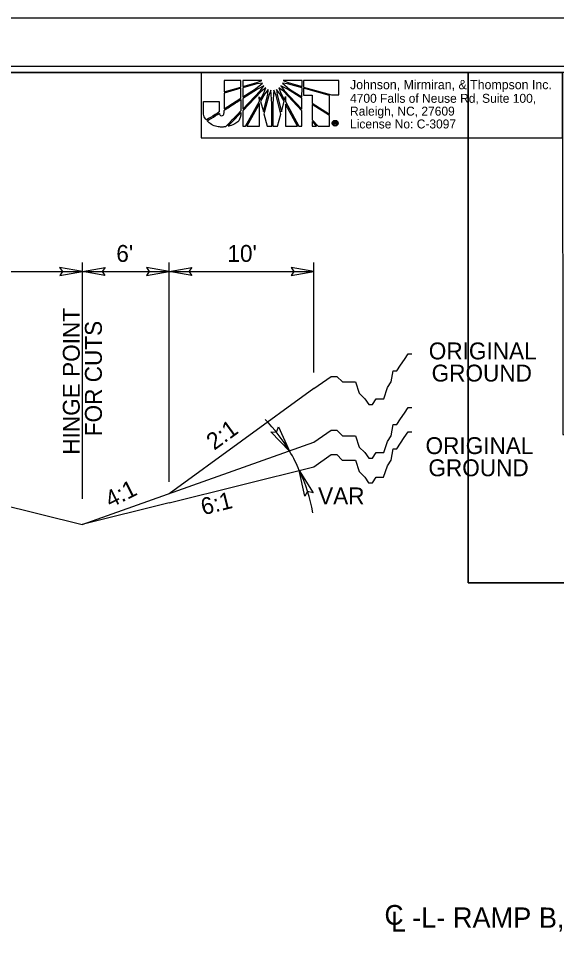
# Model space of a CAD drawing. Extents: x 1640342 to 1730599, y 538663 to 843747.
# Drawn here: x 1730088.8 to 1730133.5, y 539530.7 to 539606.6 of the extents above; entities that cross this region are included whole.
import ezdxf

# ---------------------------------------------------------------- set-up
doc = ezdxf.new("R2010")
doc.units = 0
for name, color, linetype in [('Default', 7, 'Continuous'), ('Prop Dimension Text', 7, 'Continuous'), ('Sheet Clip Boundary CELL', 7, 'Continuous'), ('Sheet Layout Plan Border', 7, 'Continuous'), ('Sheet Plan CELL', 7, 'Continuous'), ('Sheet Plan Layout CELL', 7, 'Continuous'), ('Sheet Plot Border Inside CELL', 7, 'Continuous'), ('Sheet Plot Border Outside CELL', 7, 'Continuous'), ('Typical Hinge Slope Interstate CELL', 7, 'Continuous'), ('Typical Pavement Slope CELL', 7, 'Continuous'), ('Typical Text Centerline CELL', 7, 'Continuous')]:
    doc.layers.add(name, color=color, linetype=linetype)

msp = doc.modelspace()

# ---------------------------------------------------------------- linework, layer by layer
at = {"layer": 'Default'}
for p, q in [((1730094.148, 539566.8), (1730094.148, 539586.384)), ((1730101.348, 539568.206), (1730101.348, 539586.384)), ((1730113.348, 539577.278), (1730113.348, 539586.384)), ((1730072.54, 539585.645), (1730094.141, 539585.645)), ((1730094.141, 539585.645), (1730101.341, 539585.645)), ((1730101.341, 539585.645), (1730113.341, 539585.645))]:
    msp.add_line(p, q, dxfattribs=at)
for points in [[(1730092.274, 539585.324), (1730094.148, 539585.647), (1730092.264, 539585.98), (1730092.503, 539585.647)], [(1730096.022, 539585.324), (1730094.148, 539585.647), (1730096.033, 539585.98), (1730095.793, 539585.647)], [(1730099.474, 539585.324), (1730101.348, 539585.647), (1730099.464, 539585.98), (1730099.703, 539585.647)], [(1730103.222, 539585.324), (1730101.348, 539585.647), (1730103.233, 539585.98), (1730102.993, 539585.647)], [(1730111.467, 539585.322), (1730113.341, 539585.645), (1730111.456, 539585.978), (1730111.696, 539585.645)], [(1730110.407, 539572.756), (1730111.316, 539570.761), (1730109.776, 539572.34), (1730110.248, 539572.328)], [(1730112.59, 539567.014), (1730112.124, 539569.155), (1730113.295, 539567.286), (1730112.835, 539567.398)], [(1730112.59, 539567.014), (1730112.124, 539569.155), (1730113.295, 539567.286), (1730112.835, 539567.398)]]:
    msp.add_lwpolyline(points, close=True, dxfattribs=at)
at = {"layer": 'Prop Dimension Text'}
for p, q in [((1730107.302, 539601.48), (1730105.899, 539601.478)), ((1730105.899, 539601.478), (1730105.9, 539600.548)), ((1730107.302, 539600.938), (1730107.302, 539601.48)), ((1730109.027, 539601.488), (1730107.448, 539601.487)), ((1730107.448, 539601.487), (1730107.448, 539600.984)), ((1730107.448, 539600.984), (1730108.624, 539601.31)), ((1730108.502, 539600.784), (1730109.082, 539601.257)), ((1730108.624, 539601.31), (1730109.027, 539601.488)), ((1730109.082, 539601.257), (1730108.624, 539601.201)), ((1730110.736, 539601.258), (1730111.324, 539600.777)), ((1730111.169, 539601.203), (1730110.736, 539601.258)), ((1730112.37, 539601.485), (1730110.814, 539601.49)), ((1730110.814, 539601.49), (1730111.208, 539601.305)), ((1730111.208, 539601.305), (1730112.37, 539600.98)), ((1730112.37, 539600.98), (1730112.37, 539601.485)), ((1730115.428, 539601.494), (1730112.479, 539601.492)), ((1730112.479, 539601.492), (1730112.479, 539600.95)), ((1730115.43, 539600.286), (1730115.428, 539601.494)), ((1730105.9, 539600.548), (1730107.302, 539600.938)), ((1730107.302, 539600.836), (1730105.9, 539600.441)), ((1730107.303, 539600.023), (1730107.302, 539600.836)), ((1730108.624, 539601.201), (1730107.448, 539600.876)), ((1730107.448, 539600.876), (1730107.449, 539600.116)), ((1730107.449, 539600.116), (1730108.502, 539600.784)), ((1730108.664, 539600.768), (1730107.449, 539599.993)), ((1730107.45, 539599.118), (1730108.928, 539600.659)), ((1730108.988, 539600.583), (1730107.45, 539598.97)), ((1730109.198, 539601.039), (1730108.664, 539600.768)), ((1730108.928, 539600.659), (1730109.198, 539601.039)), ((1730109.361, 539600.87), (1730108.988, 539600.583)), ((1730109.19, 539600.421), (1730109.361, 539600.87)), ((1730109.562, 539600.746), (1730109.285, 539600.389)), ((1730109.523, 539600.313), (1730109.562, 539600.746)), ((1730109.794, 539600.683), (1730109.602, 539600.234)), ((1730109.855, 539599.577), (1730109.794, 539600.683)), ((1730110.025, 539600.684), (1730109.954, 539599.577)), ((1730110.211, 539600.235), (1730110.025, 539600.684)), ((1730110.25, 539600.746), (1730110.296, 539600.297)), ((1730110.521, 539600.39), (1730110.25, 539600.746)), ((1730110.449, 539600.871), (1730110.621, 539600.422)), ((1730110.822, 539600.585), (1730110.449, 539600.871)), ((1730110.613, 539601.041), (1730110.884, 539600.654)), ((1730111.155, 539600.77), (1730110.613, 539601.041)), ((1730112.363, 539598.961), (1730110.822, 539600.585)), ((1730110.884, 539600.654), (1730112.363, 539599.107)), ((1730112.362, 539600.005), (1730111.155, 539600.77)), ((1730112.37, 539600.873), (1730111.169, 539601.203)), ((1730111.324, 539600.777), (1730112.362, 539600.13)), ((1730112.362, 539600.13), (1730112.37, 539600.873)), ((1730112.479, 539600.95), (1730112.479, 539600.934)), ((1730112.479, 539600.934), (1730114.802, 539600.285)), ((1730112.479, 539600.85), (1730112.479, 539600.841)), ((1730114.654, 539600.232), (1730112.479, 539600.85)), ((1730112.479, 539600.841), (1730112.48, 539600.276)), ((1730105.9, 539600.441), (1730105.901, 539599.133)), ((1730105.901, 539599.133), (1730107.303, 539600.023)), ((1730107.449, 539599.993), (1730107.45, 539599.118)), ((1730107.683, 539597.697), (1730108.827, 539599.77)), ((1730108.827, 539599.77), (1730108.826, 539600.141)), ((1730108.826, 539600.141), (1730108.896, 539599.886)), ((1730108.896, 539599.886), (1730109.19, 539600.421)), ((1730109.285, 539600.389), (1730108.936, 539599.754)), ((1730108.936, 539599.754), (1730109.161, 539598.912)), ((1730109.161, 539598.912), (1730109.523, 539600.313)), ((1730109.602, 539600.234), (1730109.208, 539598.717)), ((1730110.615, 539598.695), (1730110.211, 539600.235)), ((1730110.296, 539600.297), (1730110.661, 539598.881)), ((1730110.885, 539599.733), (1730110.521, 539600.39)), ((1730110.621, 539600.422), (1730110.922, 539599.865)), ((1730110.661, 539598.881), (1730110.885, 539599.733)), ((1730110.922, 539599.865), (1730110.994, 539600.143)), ((1730110.994, 539600.143), (1730110.994, 539599.733)), ((1730110.994, 539599.733), (1730112.116, 539597.701)), ((1730112.363, 539599.107), (1730112.362, 539600.005)), ((1730112.48, 539600.276), (1730113.2, 539600.277)), ((1730113.2, 539600.277), (1730113.201, 539599.603)), ((1730114.655, 539598.683), (1730114.654, 539600.232)), ((1730114.802, 539600.285), (1730115.43, 539600.286)), ((1730107.45, 539598.97), (1730107.451, 539597.697)), ((1730108.827, 539599.569), (1730107.792, 539597.697)), ((1730108.838, 539597.698), (1730108.827, 539599.569)), ((1730109.857, 539597.706), (1730109.855, 539599.577)), ((1730109.954, 539599.577), (1730109.956, 539597.706)), ((1730112.001, 539597.708), (1730110.994, 539599.531)), ((1730110.994, 539599.531), (1730110.996, 539597.707)), ((1730112.364, 539597.701), (1730112.363, 539598.961)), ((1730113.201, 539599.603), (1730114.655, 539598.683)), ((1730113.201, 539599.487), (1730113.202, 539598.232)), ((1730114.655, 539598.574), (1730113.201, 539599.487)), ((1730109.208, 539598.717), (1730109.472, 539597.706)), ((1730110.345, 539597.706), (1730110.615, 539598.695)), ((1730113.202, 539598.232), (1730113.705, 539597.703)), ((1730114.656, 539597.704), (1730114.655, 539598.574)), ((1730107.451, 539597.697), (1730107.683, 539597.697)), ((1730107.792, 539597.697), (1730108.838, 539597.698)), ((1730109.472, 539597.706), (1730109.857, 539597.706)), ((1730109.956, 539597.706), (1730110.345, 539597.706)), ((1730110.996, 539597.707), (1730112.001, 539597.708)), ((1730112.116, 539597.701), (1730112.364, 539597.701)), ((1730113.566, 539597.703), (1730113.202, 539598.096)), ((1730113.202, 539598.096), (1730113.202, 539597.702)), ((1730113.202, 539597.702), (1730113.566, 539597.703)), ((1730113.705, 539597.703), (1730114.656, 539597.704)), ((1730115.026, 539597.836), (1730115.025, 539598.051)), ((1730115.025, 539598.051), (1730115.113, 539598.051)), ((1730115.074, 539597.836), (1730115.026, 539597.836)), ((1730115.113, 539598.01), (1730115.074, 539598.01)), ((1730115.074, 539598.01), (1730115.074, 539597.959)), ((1730115.074, 539597.959), (1730115.113, 539597.959)), ((1730115.113, 539597.92), (1730115.074, 539597.92)), ((1730115.074, 539597.92), (1730115.074, 539597.836)), ((1730115.113, 539598.178), (1730115.113, 539598.133)), ((1730115.113, 539598.133), (1730115.113, 539598.178)), ((1730115.113, 539598.051), (1730115.113, 539598.01)), ((1730115.113, 539598.01), (1730115.113, 539598.051)), ((1730115.113, 539598.051), (1730115.127, 539598.051)), ((1730115.119, 539598.01), (1730115.113, 539598.01)), ((1730115.113, 539597.959), (1730115.113, 539597.92)), ((1730115.113, 539597.92), (1730115.113, 539597.959)), ((1730115.113, 539597.959), (1730115.115, 539597.959)), ((1730115.115, 539597.92), (1730115.113, 539597.92)), ((1730115.113, 539597.753), (1730115.114, 539597.706)), ((1730115.114, 539597.706), (1730115.113, 539597.753)), ((1730115.113, 539597.753), (1730115.115, 539597.753)), ((1730115.115, 539597.706), (1730115.114, 539597.706))]:
    msp.add_line(p, q, dxfattribs=at)
msp.add_lwpolyline([(1730104.001, 539596.732), (1730133.983, 539596.732), (1730133.983, 539602.142), (1730104.001, 539602.142)], close=True, dxfattribs=at)
for points in [[(1730105.9, 539600.548), (1730107.302, 539600.938), (1730107.302, 539601.48), (1730105.899, 539601.478), (1730105.9, 539600.548)], [(1730108.624, 539601.31), (1730109.027, 539601.488), (1730107.448, 539601.487), (1730107.448, 539600.984), (1730108.624, 539601.31)], [(1730107.448, 539600.876), (1730107.449, 539600.116), (1730108.502, 539600.784), (1730109.082, 539601.257), (1730108.624, 539601.201), (1730107.448, 539600.876)], [(1730110.736, 539601.258), (1730111.324, 539600.777), (1730112.362, 539600.13), (1730112.37, 539600.873), (1730111.169, 539601.203), (1730110.736, 539601.258)], [(1730111.208, 539601.305), (1730112.37, 539600.98), (1730112.37, 539601.485), (1730110.814, 539601.49), (1730111.208, 539601.305)], [(1730115.428, 539601.494), (1730112.479, 539601.492), (1730112.479, 539600.95), (1730112.479, 539600.934), (1730114.802, 539600.285), (1730115.43, 539600.286), (1730115.428, 539601.494)], [(1730105.901, 539599.133), (1730107.303, 539600.023), (1730107.302, 539600.836), (1730105.9, 539600.441), (1730105.901, 539599.133)], [(1730107.449, 539599.993), (1730107.45, 539599.118), (1730108.928, 539600.659), (1730109.198, 539601.039), (1730108.664, 539600.768), (1730107.449, 539599.993)], [(1730109.361, 539600.87), (1730108.988, 539600.583), (1730107.45, 539598.97), (1730107.451, 539597.697), (1730107.683, 539597.697), (1730108.827, 539599.77), (1730108.826, 539600.141), (1730108.896, 539599.886), (1730109.19, 539600.421), (1730109.361, 539600.87)], [(1730109.562, 539600.746), (1730109.285, 539600.389), (1730108.936, 539599.754), (1730109.161, 539598.912), (1730109.523, 539600.313), (1730109.562, 539600.746)], [(1730109.602, 539600.234), (1730109.208, 539598.717), (1730109.472, 539597.706), (1730109.857, 539597.706), (1730109.855, 539599.577), (1730109.794, 539600.683), (1730109.602, 539600.234)], [(1730110.025, 539600.684), (1730109.954, 539599.577), (1730109.956, 539597.706), (1730110.345, 539597.706), (1730110.615, 539598.695), (1730110.211, 539600.235), (1730110.025, 539600.684)], [(1730110.25, 539600.746), (1730110.296, 539600.297), (1730110.661, 539598.881), (1730110.885, 539599.733), (1730110.521, 539600.39), (1730110.25, 539600.746)], [(1730110.449, 539600.871), (1730110.621, 539600.422), (1730110.922, 539599.865), (1730110.994, 539600.143), (1730110.994, 539599.733), (1730112.116, 539597.701), (1730112.364, 539597.701), (1730112.363, 539598.961), (1730110.822, 539600.585), (1730110.449, 539600.871)], [(1730110.613, 539601.041), (1730110.884, 539600.654), (1730112.363, 539599.107), (1730112.362, 539600.005), (1730111.155, 539600.77), (1730110.613, 539601.041)], [(1730112.479, 539600.85), (1730112.479, 539600.841), (1730112.48, 539600.276), (1730113.2, 539600.277), (1730113.201, 539599.603), (1730114.655, 539598.683), (1730114.654, 539600.232), (1730112.479, 539600.85)], [(1730107.792, 539597.697), (1730108.838, 539597.698), (1730108.827, 539599.569), (1730107.792, 539597.697)], [(1730110.996, 539597.707), (1730112.001, 539597.708), (1730110.994, 539599.531), (1730110.996, 539597.707)], [(1730113.201, 539599.487), (1730113.202, 539598.232), (1730113.705, 539597.703), (1730114.656, 539597.704), (1730114.655, 539598.574), (1730113.201, 539599.487), (1730113.201, 539599.487)], [(1730113.202, 539597.702), (1730113.202, 539597.702), (1730113.566, 539597.703), (1730113.202, 539598.096), (1730113.202, 539597.702)], [(1730115.207, 539597.887), (1730115.207, 539597.875), (1730115.209, 539597.868), (1730115.209, 539597.86), (1730115.215, 539597.837), (1730115.17, 539597.836)]]:
    msp.add_lwpolyline(points, dxfattribs=at)
for points, degree in [([(1730105.497, 539599.735), (1730105.497, 539599.735), (1730104.199, 539599.733), (1730104.199, 539599.733), (1730104.199, 539599.733), (1730104.199, 539598.921), (1730104.199, 539598.921), (1730104.199, 539598.921), (1730104.199, 539598.835), (1730104.199, 539598.835), (1730104.2, 539598.58), (1730104.283, 539598.379), (1730104.432, 539598.21), (1730104.432, 539598.21), (1730105.498, 539598.859), (1730105.498, 539598.876), (1730105.498, 539598.876), (1730105.497, 539599.735), (1730105.497, 539599.735)], 3), ([(1730105.7, 539598.566), (1730105.617, 539598.565), (1730105.545, 539598.612), (1730105.515, 539598.767), (1730105.515, 539598.767), (1730104.508, 539598.143), (1730104.508, 539598.143), (1730104.819, 539597.817), (1730105.314, 539597.623), (1730105.733, 539597.623), (1730105.842, 539597.623), (1730105.925, 539597.633), (1730106.041, 539597.656), (1730106.041, 539597.656), (1730107.304, 539598.963), (1730107.304, 539598.963), (1730107.304, 539598.963), (1730107.303, 539599.908), (1730107.303, 539599.908), (1730107.303, 539599.908), (1730105.901, 539599.015), (1730105.901, 539599.015), (1730105.901, 539598.661), (1730105.816, 539598.566), (1730105.7, 539598.566)], 3), ([(1730105.7, 539598.566), (1730105.617, 539598.565), (1730105.545, 539598.612), (1730105.515, 539598.767), (1730105.515, 539598.767), (1730104.508, 539598.143), (1730104.508, 539598.143), (1730104.819, 539597.817), (1730105.314, 539597.623), (1730105.733, 539597.623), (1730105.842, 539597.623), (1730105.925, 539597.633), (1730106.041, 539597.656), (1730106.041, 539597.656), (1730107.304, 539598.963), (1730107.304, 539598.963), (1730107.304, 539598.963), (1730107.303, 539599.908), (1730107.303, 539599.908), (1730107.303, 539599.908), (1730105.901, 539599.015), (1730105.901, 539599.015), (1730105.901, 539598.661), (1730105.816, 539598.566), (1730105.7, 539598.566)], 3), ([(1730107.304, 539598.815), (1730107.304, 539598.815), (1730106.212, 539597.686), (1730106.212, 539597.686), (1730106.747, 539597.819), (1730107.279, 539598.173), (1730107.304, 539598.815)], 3), ([(1730115.114, 539597.706), (1730115.049, 539597.706), (1730114.993, 539597.729), (1730114.946, 539597.776), (1730114.899, 539597.821), (1730114.875, 539597.877), (1730114.875, 539597.943), (1730114.875, 539598.01), (1730114.899, 539598.066), (1730114.945, 539598.109), (1730114.992, 539598.154), (1730115.047, 539598.178), (1730115.113, 539598.178)], 3), ([(1730115.113, 539598.133), (1730115.06, 539598.133), (1730115.016, 539598.115), (1730114.979, 539598.08), (1730114.942, 539598.043), (1730114.922, 539597.996), (1730114.922, 539597.943), (1730114.922, 539597.891), (1730114.942, 539597.844), (1730114.979, 539597.807), (1730115.016, 539597.77), (1730115.061, 539597.753), (1730115.113, 539597.753)], 3), ([(1730115.113, 539598.178), (1730115.179, 539598.178), (1730115.236, 539598.154), (1730115.283, 539598.11), (1730115.33, 539598.067), (1730115.353, 539598.01), (1730115.353, 539597.944)], 3), ([(1730115.115, 539597.753), (1730115.168, 539597.753), (1730115.213, 539597.77), (1730115.25, 539597.807), (1730115.287, 539597.844), (1730115.306, 539597.891), (1730115.306, 539597.944), (1730115.306, 539597.997), (1730115.287, 539598.043), (1730115.25, 539598.08), (1730115.213, 539598.115), (1730115.168, 539598.133), (1730115.113, 539598.133)], 3), ([(1730115.115, 539597.959), (1730115.146, 539597.959), (1730115.162, 539597.969), (1730115.162, 539597.987), (1730115.162, 539598.002), (1730115.148, 539598.01), (1730115.119, 539598.01)], 3), ([(1730115.353, 539597.944), (1730115.353, 539597.878), (1730115.33, 539597.821), (1730115.285, 539597.774), (1730115.238, 539597.729), (1730115.182, 539597.706), (1730115.115, 539597.706)], 3), ([(1730115.152, 539597.912), (1730115.146, 539597.916), (1730115.135, 539597.92), (1730115.115, 539597.92)], 2), ([(1730115.127, 539598.051), (1730115.181, 539598.051), (1730115.209, 539598.03), (1730115.209, 539597.987), (1730115.209, 539597.967), (1730115.201, 539597.952), (1730115.184, 539597.94)], 3), ([(1730115.17, 539597.836), (1730115.164, 539597.848), (1730115.16, 539597.86), (1730115.16, 539597.875), (1730115.16, 539597.895), (1730115.158, 539597.907), (1730115.152, 539597.912)], 3), ([(1730115.184, 539597.94), (1730115.197, 539597.932), (1730115.205, 539597.915), (1730115.207, 539597.887)], 2)]:
    msp.add_open_spline(points, degree=degree, dxfattribs=at)
at = {"layer": 'Sheet Clip Boundary CELL'}
msp.add_lwpolyline([(1729883.99, 539392.14), (1730163.993, 539392.14), (1730163.993, 539559.842), (1730126.14, 539559.842), (1730126.14, 539602.14), (1729883.99, 539602.14)], close=True, dxfattribs=at)
at = {"layer": 'Sheet Layout Plan Border'}
msp.add_lwpolyline([(1729883.99, 539392.14), (1730163.993, 539392.14), (1730163.993, 539559.842), (1730126.14, 539559.842), (1730126.14, 539602.14), (1729883.99, 539602.14)], close=True, dxfattribs=at)
at = {"layer": 'Sheet Plan CELL'}
for points in [[(1729873.99, 539392.14), (1729873.985, 539602.135), (1730133.983, 539602.142), (1730133.985, 539572.13), (1730173.993, 539572.127), (1730173.993, 539392.14)], [(1730173.998, 539602.14), (1729873.99, 539602.14), (1729873.99, 539392.14), (1730173.993, 539392.14)]]:
    msp.add_lwpolyline(points, close=True, dxfattribs=at)
at = {"layer": 'Sheet Plan Layout CELL'}
for points in [[(1729873.985, 539602.135), (1729873.99, 539392.14), (1730173.99, 539392.14), (1730173.99, 539559.842), (1730126.14, 539559.842), (1730126.14, 539602.14)], [(1730126.14, 539559.842), (1730173.995, 539559.842), (1730174, 539602.14), (1730126.14, 539602.14)]]:
    msp.add_lwpolyline(points, close=True, dxfattribs=at)
at = {"layer": 'Sheet Plot Border Inside CELL'}
msp.add_lwpolyline([(1729843.293, 539391.637), (1730176.49, 539391.64), (1730176.493, 539602.637), (1729843.293, 539602.637)], close=True, dxfattribs=at)
at = {"layer": 'Sheet Plot Border Outside CELL'}
msp.add_lwpolyline([(1729840.693, 539387.637), (1730177.393, 539387.637), (1730177.393, 539606.637), (1729840.693, 539606.637)], close=True, dxfattribs=at)
at = {"layer": 'Typical Hinge Slope Interstate CELL'}
for points in [[(1730113.341, 539575.94), (1730114.783, 539576.952), (1730115.25, 539576.952), (1730115.717, 539576.487), (1730116.028, 539576.487), (1730116.495, 539576.487), (1730116.806, 539576.487), (1730117.118, 539575.55), (1730117.585, 539575.085), (1730117.896, 539574.616), (1730118.207, 539574.616), (1730118.519, 539575.085), (1730118.83, 539575.085), (1730119.141, 539575.085), (1730119.452, 539576.019), (1730119.763, 539576.487), (1730119.92, 539577.421), (1730120.231, 539577.421), (1730120.542, 539577.886), (1730120.853, 539578.355), (1730121.164, 539578.823), (1730121.476, 539578.823)], [(1730113.341, 539571.481), (1730114.783, 539572.493), (1730115.25, 539572.493), (1730115.717, 539572.028), (1730116.028, 539572.028), (1730116.495, 539572.028), (1730116.806, 539572.028), (1730117.118, 539571.091), (1730117.585, 539570.626), (1730117.896, 539570.157), (1730118.207, 539570.157), (1730118.519, 539570.626), (1730118.83, 539570.626), (1730119.141, 539570.626), (1730119.452, 539571.56), (1730119.763, 539572.028), (1730119.92, 539572.962), (1730120.231, 539572.962), (1730120.542, 539573.427), (1730120.853, 539573.895), (1730121.164, 539574.364), (1730121.476, 539574.364)], [(1730113.334, 539569.458), (1730114.776, 539570.47), (1730115.244, 539570.47), (1730115.71, 539570.005), (1730116.021, 539570.005), (1730116.489, 539570.005), (1730116.8, 539570.005), (1730117.111, 539569.068), (1730117.579, 539568.603), (1730117.89, 539568.134), (1730118.201, 539568.134), (1730118.512, 539568.603), (1730118.823, 539568.603), (1730119.135, 539568.603), (1730119.446, 539569.537), (1730119.757, 539570.005), (1730119.913, 539570.939), (1730120.224, 539570.939), (1730120.536, 539571.404), (1730120.847, 539571.873), (1730121.158, 539572.341), (1730121.469, 539572.341)]]:
    msp.add_lwpolyline(points, dxfattribs=at)
for centre, start, end in [((1730100.845, 539564.776), 29.75191, 45.50364), ((1730101.336, 539563.76), 8.9538, 26.57006), ((1730101.336, 539563.76), 8.9538, 26.57006)]:
    msp.add_arc(centre, 12.061, start, end, dxfattribs=at)
msp.add_ellipse((1730101.226, 539571.367), major_axis=(10.885, -5.195), ratio=0.5, start_param=0.463735, end_param=0.681536, dxfattribs=at)
at = {"layer": 'Typical Pavement Slope CELL'}
for p, q in [((1730113.341, 539575.94), (1730101.356, 539567.223)), ((1730094.137, 539564.658), (1730113.341, 539571.481)), ((1730072.542, 539570.057), (1730094.139, 539564.658)), ((1730101.336, 539566.458), (1730113.334, 539569.458)), ((1730101.336, 539566.458), (1730094.137, 539564.658))]:
    msp.add_line(p, q, dxfattribs=at)

# ---------------------------------------------------------------- texts
at = {"layer": 'Prop Dimension Text'}
for s, height, rotation, p in [('Johnson, Mirmiran, & Thompson Inc.', 0.76607, 360, (1730116.348, 539600.757)), ('4700 Falls of Neuse Rd, Suite 100, ', 0.74418, 360, (1730116.348, 539599.632)), ('Raleigh, NC, 27609', 0.74418, 360, (1730116.348, 539598.569)), ('License No: C-3097', 0.74418, 360, (1730116.348, 539597.506)), ('HINGE POINT', 1.4, 90, (1730093.931, 539570.454)), ('FOR CUTS', 1.4, 90, (1730095.766, 539571.985)), ('2:1', 1.4, 36.02984, (1730105.089, 539570.779)), ('4:1', 1.4, 26.57006, (1730096.48, 539566.015)), ('6:1', 1.4, 14.03809, (1730104.175, 539565.427))]:
    msp.add_text(s, height=height, rotation=rotation, dxfattribs=at).set_placement(p)
for s, p in [("6'", (1730096.965, 539586.445)), ("10'", (1730106.179, 539586.445)), ('ORIGINAL', (1730122.879, 539578.358)), ('GROUND', (1730123.114, 539576.522)), ('ORIGINAL', (1730122.61, 539570.505)), ('GROUND', (1730122.846, 539568.669)), ('VAR', (1730113.7, 539566.336))]:
    msp.add_text(s, height=1.4, dxfattribs=at).set_placement(p)
at = {"layer": 'Typical Text Centerline CELL'}
for s, height, rotation, p in [('C', 1.639, 0.04425, (1730119.205, 539531.476)), ('-L- RAMP B, -L- RAMP D', 1.68295, 359.94168, (1730121.504, 539531.238)), ('L', 1.64, 359.99115, (1730119.75, 539530.917))]:
    msp.add_text(s, height=height, rotation=rotation, dxfattribs=at).set_placement(p)

doc.saveas('drawing.dxf')
